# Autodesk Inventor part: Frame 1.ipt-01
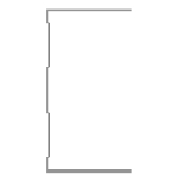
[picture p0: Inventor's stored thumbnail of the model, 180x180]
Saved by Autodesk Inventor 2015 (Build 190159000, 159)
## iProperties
_CCFamilyMember: 1
_CCFamilyDisplayName: Kévin - Kévin Novo
_FrameMemberDoc: Frame Member File
_Version: 15.0.0
_GetPNFromCC: 1
Created: 2015-04
Part Number: Frame 1.ipt-01
Material: Aluminum 6061
Description: Kévin Novo
Document SubType Name: Modeling
Standard: Kevin
Designer: suporte
Standards Organization: Kevin
Language: en-US
Size Designation: (Unnamed 1)
Categories: <MemberInstance><Categories><Category DisplayName="Structural Shapes" InternalName="089c4875-fa83-4c05-b084-43b9cc11f5ed" Mnemonic="GRDR"><CategoryParameter Dis
Density: 2.7 g/cm^3
Appearance: Aluminum - Flat
IsCustomPart: 1
G_L: 1150,000 mm
G_W: 50,000 mm
G_H: 75,000 mm
+45B8A6D9-03A5-49AF-AB0C-45E396BDBBF2+CUTDETAIL1: Cut
+657C0FA2-9EC3-4FA9-9A37-8D1E4F84BB90+CUTDETAIL2: Cut
Author: suporte
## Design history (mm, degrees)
node "Start Plane"
node "End Plane"
sketch "Sketch"
  geometry: L1 (24.7, 37.5)-(24.7, 36.9); L2 (24.7, 36.9)-(-24.7, 36.9); L3 (-24.7, -36.9)-(24.7, -36.9); L4 (24.7, -36.9)-(24.7, -37.5); L5 (24.7, -37.5)-(-25.3, -37.5); L6 (-25.3, 37.5)-(24.7, 37.5); L7 (-24.7, 36.9)-(-24.7, 31.9); L8 (-24.7, 31.9)-(-23.3, 30.5); L9 (-23.3, 30.5)-(-23.3, 10.934); L10 (-23.3, 10.934)-(-24.7, 9.534); L11 (-24.7, 9.534)-(-24.7, -9.534); L12 (-24.7, -9.534)-(-23.3, -10.934); L13 (-23.3, -10.934)-(-23.3, -30.5); L14 (-23.3, -30.5)-(-24.7, -31.9); L15 (-24.7, -31.9)-(-24.7, -36.9); L16 (-25.3, -37.5)-(-25.3, -31.651); L17 (-25.3, -31.651)-(-23.9, -30.251); L18 (-23.9, -30.251)-(-23.9, -11.183); L19 (-23.9, -11.183)-(-25.3, -9.783); L20 (-25.3, -9.783)-(-25.3, 9.783); L21 (-25.3, 9.783)-(-23.9, 11.183); L22 (-23.9, 11.183)-(-23.9, 30.251); L23 (-23.9, 30.251)-(-25.3, 31.651); L24 (-25.3, 31.651)-(-25.3, 37.5); L25 (-25.3, 0)-(30.37, 0); 3 further points
  constraints: 50 end point, 10 point on line, 9 parallel, 5 perpendicular, 4 equal length, 3 midpoint, 3 vertical, 2 vertical alignment, 1 collinear, 1 horizontal, 1 horizontal alignment
  dimensions: "d3" = 0.6 distance of L1.start L1.end (= d6); "d5" = 75 distance between parallel lines of L5 L6; "d6" = 0.6 distance between parallel lines of L24 L7 (= d8); "d7" = 0.6 distance between parallel lines of L8 L23 (= d8); "d8" = 0.6 distance between parallel lines of L22 L9 (= d12); "Espessura" = 0.6 distance between parallel lines of L17 L14; "d10" = 0.6 distance between parallel lines of L13 L18 (= Espessura); "d11" = 0.6 distance between parallel lines of L12 L19 (= Espessura); "d12" = 0.6 distance between parallel lines of L21 L10 (= d11); "d13" = 5 distance of L2.end L7.end; "d15" = 135 deg angle of L9 L8; "d16" = 2 distance between parallel lines of L24 L9; "d17" = 50 distance of L6.start L1.start
extrude "Body" join sketch "Sketch" stored distance "d24" = 0.13; taper "d25" = 0 deg
node "Driven Length"
  sketch "Sketch10"
    geometry: L1 (0, 0)-(10, 0) reference
    constraints: 2 end point, 1 horizontal
  workplane "Work Plane7"
  sketch "Sketch11"
    geometry: L1 (-2, 12.5)-(12, 12.5) reference; L2 (-2, 1162.5)-(12, 1162.5) reference
    dimensions: "d27" = 1150 distance between parallel lines of L1 L2 (derived)
workplane "Work Plane8"
split "Split1"
workplane "Work Plane9"
split "Split2"
body "Solid1"
other parameters: "G_OFFSET_START" = -12.5 [user parameter; used in 1 equation term], "G_OFFSET_END" = -37.5 [user parameter; used in 1 equation term], "d22" = 12.5 (= -G_OFFSET_START), "d23" = 1162.5 (= tamanho + G_OFFSET_END), "G_L" = 1150 (= d27) [user parameter], "d34" = 90 deg
